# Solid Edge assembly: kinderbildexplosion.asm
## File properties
Author: Susi
Template: Normal.asm
Last saved by: Susi
Revision: 1
Application: Solid Edge
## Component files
Holzrahmen5.asm
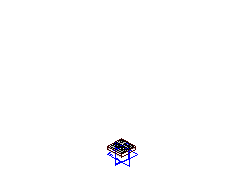
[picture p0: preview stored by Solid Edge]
